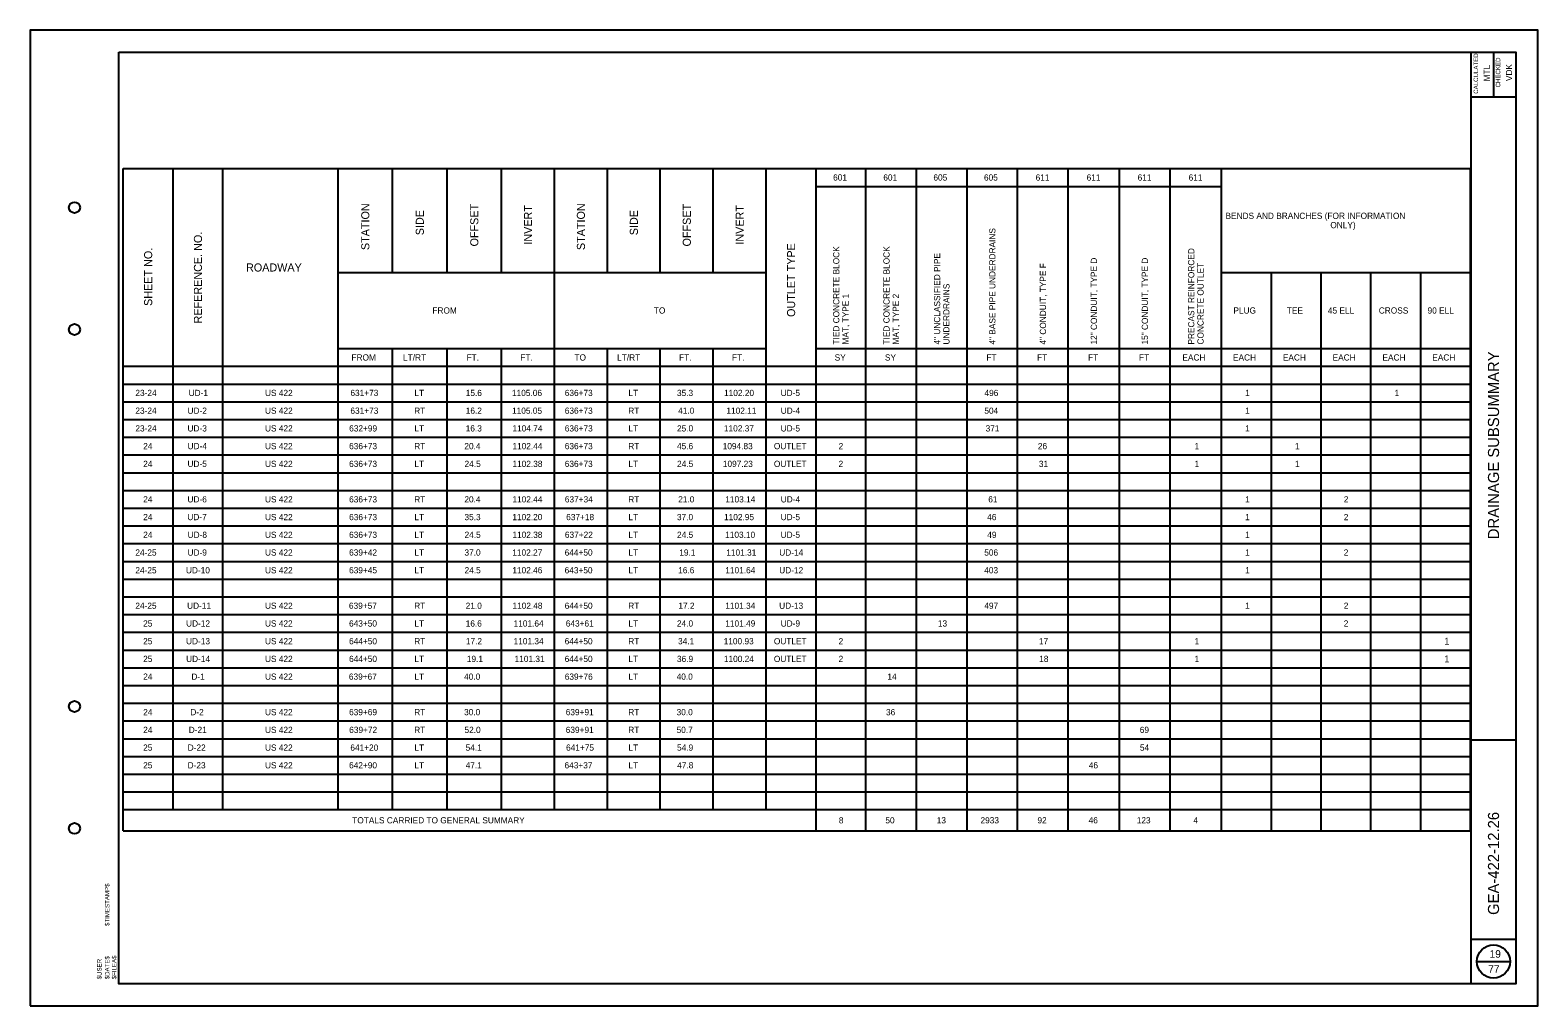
# Model space of a CAD drawing. Extents: x 0 to 34, y 0 to 22.
import ezdxf

# ---------------------------------------------------------------- set-up
doc = ezdxf.new("R2010")
doc.units = 0
for name, color, linetype in [('SH_Border', 7, 'Continuous'), ('SH_Cut_Line', 7, 'Continuous'), ('SH_Data', 7, 'Continuous'), ('SH_Text', 7, 'Continuous')]:
    doc.layers.add(name, color=color, linetype=linetype)

msp = doc.modelspace()

# ---------------------------------------------------------------- linework, layer by layer
at = {"layer": 'SH_Border'}
for p, q in [((32.5, 0.5), (32.5, 21.5)), ((33, 21.5), (33, 20.5)), ((32.5, 20.5), (33.5, 20.5)), ((32.5, 6), (33.5, 6)), ((32.5, 1.5), (33.5, 1.5))]:
    msp.add_line(p, q, dxfattribs=at)
msp.add_lwpolyline([(2, 21.5), (33.5, 21.5), (33.5, 0.5), (2, 0.5)], close=True, dxfattribs=at)
for centre in [(1, 18), (1, 15.25), (1, 6.75), (1, 4)]:
    msp.add_circle(centre, 0.125, dxfattribs=at)
at = {"layer": 'SH_Cut_Line'}
msp.add_lwpolyline([(0, 0), (34, 0), (34, 22), (0, 22)], close=True, dxfattribs=at)
at = {"layer": 'SH_Data'}
msp.add_line((32.625, 1), (33.375, 1), dxfattribs=at)
msp.add_circle((33, 1), 0.375, dxfattribs=at)
at = {"layer": 'SH_Text'}
for p, q in [((2.099, 18.878), (2.099, 18.878)), ((2.099, 18.878), (32.484, 18.878)), ((2.099, 3.944), (2.099, 18.878)), ((3.222, 4.424), (3.222, 18.878)), ((4.346, 4.424), (4.346, 18.878)), ((6.944, 4.424), (6.944, 18.878)), ((8.172, 16.539), (8.172, 18.878)), ((9.401, 16.539), (9.401, 18.878)), ((10.63, 16.539), (10.63, 18.878)), ((11.824, 4.424), (11.824, 18.878)), ((13.017, 16.539), (13.017, 18.878)), ((14.211, 16.539), (14.211, 18.878)), ((15.405, 16.539), (15.405, 18.878)), ((16.598, 4.424), (16.598, 18.878)), ((17.722, 3.944), (17.722, 18.878)), ((18.845, 3.944), (18.845, 18.878)), ((19.986, 3.944), (19.986, 18.878)), ((21.127, 3.944), (21.127, 18.878)), ((22.268, 3.944), (22.268, 18.878)), ((23.409, 3.944), (23.409, 18.878)), ((24.568, 3.944), (24.568, 18.878)), ((25.709, 3.944), (25.709, 18.878)), ((26.867, 3.944), (26.867, 18.878)), ((32.484, 3.944), (32.484, 18.878)), ((17.722, 18.478), (26.867, 18.478)), ((6.944, 16.539), (16.598, 16.539)), ((26.867, 16.539), (32.484, 16.539)), ((27.991, 3.944), (27.991, 16.539)), ((29.114, 3.944), (29.114, 16.539)), ((30.237, 3.944), (30.237, 16.539)), ((31.361, 3.944), (31.361, 16.539)), ((6.944, 14.82), (16.598, 14.82)), ((8.172, 4.424), (8.172, 14.82)), ((9.401, 4.424), (9.401, 14.82)), ((10.63, 4.424), (10.63, 14.82)), ((13.017, 4.424), (13.017, 14.82)), ((14.211, 4.424), (14.211, 14.82)), ((15.405, 4.424), (15.405, 14.82)), ((17.722, 14.82), (32.484, 14.82)), ((2.099, 14.42), (32.484, 14.42)), ((16.598, 14.42), (32.484, 14.42)), ((2.099, 14.02), (32.484, 14.02)), ((2.099, 13.62), (32.484, 13.62)), ((2.099, 13.22), (32.484, 13.22)), ((2.099, 12.821), (32.484, 12.821)), ((2.099, 12.421), (32.484, 12.421)), ((2.099, 12.021), (32.484, 12.021)), ((2.099, 11.621), (32.484, 11.621)), ((2.099, 11.221), (32.484, 11.221)), ((2.099, 10.821), (32.484, 10.821)), ((2.099, 10.422), (32.484, 10.422)), ((2.099, 10.022), (32.484, 10.022)), ((2.099, 9.622), (32.484, 9.622)), ((2.099, 9.222), (32.484, 9.222)), ((2.099, 8.822), (32.484, 8.822)), ((2.099, 8.422), (32.484, 8.422)), ((2.099, 8.023), (32.484, 8.023)), ((2.099, 7.623), (32.484, 7.623)), ((2.099, 7.223), (32.484, 7.223)), ((2.099, 6.823), (32.484, 6.823)), ((2.099, 6.423), (32.484, 6.423)), ((2.099, 6.023), (32.484, 6.023)), ((2.099, 5.624), (32.484, 5.624)), ((2.099, 5.224), (32.484, 5.224)), ((2.099, 4.824), (32.484, 4.824)), ((2.099, 4.424), (32.484, 4.424)), ((2.099, 3.944), (32.484, 3.944))]:
    msp.add_line(p, q, dxfattribs=at)

# ---------------------------------------------------------------- texts
at = {"layer": 'SH_Data'}
for s, height, rotation, p in [('CALCULATED', 0.1, 90, (32.652, 20.565)), ('MTL', 0.14, 90, (32.92, 20.844)), ('CHECKED', 0.1, 90, (33.152, 20.708)), ('VDK', 0.14, 90, (33.42, 20.851)), ('DRAINAGE SUBSUMMARY', 0.25, 90, (33.125, 10.521)), (' GEA-422-12.26 ', 0.25, 90, (33.125, 1.957)), ('$TIMESTAMP$', 0.1, 89.9931, (1.788, 1.8)), ('$USER', 0.1, 89.9931, (1.611, 0.598)), ('$DATE$', 0.1, 89.9931, (1.788, 0.598)), ('$FILEA$', 0.1, 89.9931, (1.944, 0.598))]:
    msp.add_text(s, height=height, rotation=rotation, dxfattribs=at).set_placement(p)
for s, p in [('19', (32.913, 1.085)), ('77', (32.882, 0.745))]:
    msp.add_text(s, height=0.17, dxfattribs=at).set_placement(p)
at = {"layer": 'SH_Text'}
for s, height, p in [('601', 0.14, (18.108, 18.608)), ('601', 0.14, (19.24, 18.608)), ('605', 0.14, (20.369, 18.608)), ('605', 0.14, (21.51, 18.608)), ('611', 0.14, (22.675, 18.608)), ('611', 0.14, (23.825, 18.608)), ('611', 0.14, (24.975, 18.608)), ('611', 0.14, (26.125, 18.608)), ('BENDS AND BRANCHES (FOR INFORMATION', 0.14, (26.956, 17.744)), ('ONLY)', 0.14, (29.32, 17.534)), ('ROADWAY', 0.182, (4.868, 16.558)), ('FROM', 0.14, (9.071, 15.609)), ('TO', 0.14, (14.065, 15.609)), ('PLUG', 0.14, (27.135, 15.609)), ('TEE', 0.14, (28.339, 15.609)), ('45 ELL', 0.14, (29.266, 15.609)), ('CROSS', 0.14, (30.413, 15.609)), ('90 ELL', 0.14, (31.513, 15.609)), ('FROM', 0.14, (7.246, 14.55)), ('LT/RT', 0.14, (8.409, 14.55)), ('FT.', 0.14, (9.841, 14.55)), ('FT.', 0.14, (11.053, 14.55)), ('TO', 0.14, (12.275, 14.55)), ('LT/RT', 0.14, (13.237, 14.55)), ('FT.', 0.14, (14.634, 14.55)), ('FT.', 0.14, (15.827, 14.55)), ('SY', 0.14, (18.143, 14.55)), ('SY', 0.14, (19.276, 14.55)), ('FT', 0.14, (21.566, 14.55)), ('FT', 0.14, (22.707, 14.55)), ('FT', 0.14, (23.857, 14.55)), ('FT', 0.14, (25.006, 14.55)), ('EACH', 0.14, (25.984, 14.55)), ('EACH', 0.14, (27.125, 14.55)), ('EACH', 0.14, (28.249, 14.55)), ('EACH', 0.14, (29.372, 14.55)), ('EACH', 0.14, (30.496, 14.55)), ('EACH', 0.14, (31.619, 14.55)), ('23-24', 0.14, (2.373, 13.75)), ('UD-1', 0.14, (3.573, 13.75)), ('US 422', 0.14, (5.296, 13.75)), ('631+73', 0.14, (7.222, 13.75)), ('LT', 0.14, (8.665, 13.75)), ('15.6', 0.14, (9.823, 13.75)), ('1105.06', 0.14, (10.866, 13.75)), ('636+73', 0.14, (12.056, 13.75)), ('LT', 0.14, (13.492, 13.75)), ('35.3', 0.14, (14.586, 13.75)), ('1102.20', 0.14, (15.648, 13.75)), ('UD-5', 0.14, (16.924, 13.75)), ('496', 0.14, (21.521, 13.75)), ('1', 0.14, (27.4, 13.75)), ('1', 0.14, (30.77, 13.75)), ('23-24', 0.14, (2.373, 13.35)), ('UD-2', 0.14, (3.549, 13.35)), ('US 422', 0.14, (5.296, 13.35)), ('631+73', 0.14, (7.222, 13.35)), ('RT', 0.14, (8.661, 13.35)), ('16.2', 0.14, (9.823, 13.35)), ('1105.05', 0.14, (10.867, 13.35)), ('636+73', 0.14, (12.056, 13.35)), ('RT', 0.14, (13.488, 13.35)), ('41.0', 0.14, (14.613, 13.35)), ('1102.11', 0.14, (15.701, 13.35)), ('UD-4', 0.14, (16.926, 13.35)), ('504', 0.14, (21.518, 13.35)), ('1', 0.14, (27.4, 13.35)), ('23-24', 0.14, (2.373, 12.951)), ('UD-3', 0.14, (3.548, 12.951)), ('US 422', 0.14, (5.296, 12.951)), ('632+99', 0.14, (7.194, 12.951)), ('LT', 0.14, (8.665, 12.951)), ('16.3', 0.14, (9.822, 12.951)), ('1104.74', 0.14, (10.876, 12.951)), ('636+73', 0.14, (12.056, 12.951)), ('LT', 0.14, (13.492, 12.951)), ('25.0', 0.14, (14.587, 12.951)), ('1102.37', 0.14, (15.645, 12.951)), ('UD-5', 0.14, (16.924, 12.951)), ('371', 0.14, (21.547, 12.951)), ('1', 0.14, (27.4, 12.951)), ('24', 0.14, (2.549, 12.551)), ('UD-4', 0.14, (3.55, 12.551)), ('US 422', 0.14, (5.296, 12.551)), ('636+73', 0.14, (7.193, 12.551)), ('RT', 0.14, (8.661, 12.551)), ('20.4', 0.14, (9.792, 12.551)), ('1102.44', 0.14, (10.876, 12.551)), ('636+73', 0.14, (12.056, 12.551)), ('RT', 0.14, (13.488, 12.551)), ('45.6', 0.14, (14.587, 12.551)), ('1094.83', 0.14, (15.618, 12.551)), ('OUTLET', 0.14, (16.772, 12.551)), ('2', 0.14, (18.231, 12.551)), ('26', 0.14, (22.725, 12.551)), ('1', 0.14, (26.259, 12.551)), ('1', 0.14, (28.523, 12.551)), ('24', 0.14, (2.549, 12.151)), ('UD-5', 0.14, (3.548, 12.151)), ('US 422', 0.14, (5.296, 12.151)), ('636+73', 0.14, (7.193, 12.151)), ('LT', 0.14, (8.665, 12.151)), ('24.5', 0.14, (9.796, 12.151)), ('1102.38', 0.14, (10.876, 12.151)), ('636+73', 0.14, (12.056, 12.151)), ('LT', 0.14, (13.492, 12.151)), ('24.5', 0.14, (14.588, 12.151)), ('1097.23', 0.14, (15.621, 12.151)), ('OUTLET', 0.14, (16.772, 12.151)), ('2', 0.14, (18.231, 12.151)), ('31', 0.14, (22.748, 12.151)), ('1', 0.14, (26.259, 12.151)), ('1', 0.14, (28.523, 12.151)), ('24', 0.14, (2.549, 11.351)), ('UD-6', 0.14, (3.548, 11.351)), ('US 422', 0.14, (5.296, 11.351)), ('636+73', 0.14, (7.193, 11.351)), ('RT', 0.14, (8.661, 11.351)), ('20.4', 0.14, (9.792, 11.351)), ('1102.44', 0.14, (10.876, 11.351)), ('637+34', 0.14, (12.058, 11.351)), ('RT', 0.14, (13.488, 11.351)), ('21.0', 0.14, (14.614, 11.351)), ('1103.14', 0.14, (15.676, 11.351)), ('UD-4', 0.14, (16.926, 11.351)), ('61', 0.14, (21.607, 11.351)), ('1', 0.14, (27.4, 11.351)), ('2', 0.14, (29.623, 11.351)), ('24', 0.14, (2.549, 10.951)), ('UD-7', 0.14, (3.545, 10.951)), ('US 422', 0.14, (5.296, 10.951)), ('636+73', 0.14, (7.193, 10.951)), ('LT', 0.14, (8.665, 10.951)), ('35.3', 0.14, (9.794, 10.951)), ('1102.20', 0.14, (10.874, 10.951)), ('637+18', 0.14, (12.088, 10.951)), ('LT', 0.14, (13.492, 10.951)), ('37.0', 0.14, (14.586, 10.951)), ('1102.95', 0.14, (15.648, 10.951)), ('UD-5', 0.14, (16.924, 10.951)), ('46', 0.14, (21.582, 10.951)), ('1', 0.14, (27.4, 10.951)), ('2', 0.14, (29.623, 10.951)), ('24', 0.14, (2.549, 10.552)), ('UD-8', 0.14, (3.551, 10.552)), ('US 422', 0.14, (5.296, 10.552)), ('636+73', 0.14, (7.193, 10.552)), ('LT', 0.14, (8.665, 10.552)), ('24.5', 0.14, (9.796, 10.552)), ('1102.38', 0.14, (10.876, 10.552)), ('637+22', 0.14, (12.059, 10.552)), ('LT', 0.14, (13.492, 10.552)), ('24.5', 0.14, (14.588, 10.552)), ('1103.10', 0.14, (15.673, 10.552)), ('UD-5', 0.14, (16.924, 10.552)), ('49', 0.14, (21.584, 10.552)), ('1', 0.14, (27.4, 10.552)), ('24-25', 0.14, (2.372, 10.152)), ('UD-9', 0.14, (3.549, 10.152)), ('US 422', 0.14, (5.296, 10.152)), ('639+42', 0.14, (7.193, 10.152)), ('LT', 0.14, (8.665, 10.152)), ('37.0', 0.14, (9.794, 10.152)), ('1102.27', 0.14, (10.873, 10.152)), ('644+50', 0.14, (12.054, 10.152)), ('LT', 0.14, (13.492, 10.152)), ('19.1', 0.14, (14.639, 10.152)), ('1101.31', 0.14, (15.699, 10.152)), ('UD-14', 0.14, (16.893, 10.152)), ('506', 0.14, (21.516, 10.152)), ('1', 0.14, (27.4, 10.152)), ('2', 0.14, (29.623, 10.152)), ('24-25', 0.14, (2.372, 9.752)), ('UD-10', 0.14, (3.513, 9.752)), ('US 422', 0.14, (5.296, 9.752)), ('639+45', 0.14, (7.192, 9.752)), ('LT', 0.14, (8.665, 9.752)), ('24.5', 0.14, (9.796, 9.752)), ('1102.46', 0.14, (10.874, 9.752)), ('643+50', 0.14, (12.053, 9.752)), ('LT', 0.14, (13.492, 9.752)), ('16.6', 0.14, (14.614, 9.752)), ('1101.64', 0.14, (15.676, 9.752)), ('UD-12', 0.14, (16.892, 9.752)), ('403', 0.14, (21.515, 9.752)), ('1', 0.14, (27.4, 9.752)), ('24-25', 0.14, (2.372, 8.952)), ('UD-11', 0.14, (3.539, 8.952)), ('US 422', 0.14, (5.296, 8.952)), ('639+57', 0.14, (7.189, 8.952)), ('RT', 0.14, (8.661, 8.952)), ('21.0', 0.14, (9.822, 8.952)), ('1102.48', 0.14, (10.877, 8.952)), ('644+50', 0.14, (12.054, 8.952)), ('RT', 0.14, (13.488, 8.952)), ('17.2', 0.14, (14.618, 8.952)), ('1101.34', 0.14, (15.676, 8.952)), ('UD-13', 0.14, (16.891, 8.952)), ('497', 0.14, (21.518, 8.952)), ('1', 0.14, (27.4, 8.952)), ('2', 0.14, (29.623, 8.952)), ('25', 0.14, (2.548, 8.552)), ('UD-12', 0.14, (3.516, 8.552)), ('US 422', 0.14, (5.296, 8.552)), ('643+50', 0.14, (7.191, 8.552)), ('LT', 0.14, (8.665, 8.552)), ('16.6', 0.14, (9.822, 8.552)), ('1101.64', 0.14, (10.902, 8.552)), ('643+61', 0.14, (12.079, 8.552)), ('LT', 0.14, (13.492, 8.552)), ('24.0', 0.14, (14.586, 8.552)), ('1101.49', 0.14, (15.676, 8.552)), ('UD-9', 0.14, (16.925, 8.552)), ('13', 0.14, (20.47, 8.552)), ('2', 0.14, (29.623, 8.552)), ('25', 0.14, (2.548, 8.152)), ('UD-13', 0.14, (3.515, 8.152)), ('US 422', 0.14, (5.296, 8.152)), ('644+50', 0.14, (7.192, 8.152)), ('RT', 0.14, (8.661, 8.152)), ('17.2', 0.14, (9.826, 8.152)), ('1101.34', 0.14, (10.902, 8.152)), ('644+50', 0.14, (12.054, 8.152)), ('RT', 0.14, (13.488, 8.152)), ('34.1', 0.14, (14.611, 8.152)), ('1100.93', 0.14, (15.64, 8.152)), ('OUTLET', 0.14, (16.772, 8.152)), ('2', 0.14, (18.231, 8.152)), ('17', 0.14, (22.749, 8.152)), ('1', 0.14, (26.259, 8.152)), ('1', 0.154, (31.891, 8.145)), ('25', 0.14, (2.548, 7.753)), ('UD-14', 0.14, (3.517, 7.753)), ('US 422', 0.14, (5.296, 7.753)), ('644+50', 0.14, (7.192, 7.753)), ('LT', 0.14, (8.665, 7.753)), ('19.1', 0.14, (9.847, 7.753)), ('1101.31', 0.14, (10.924, 7.753)), ('644+50', 0.14, (12.054, 7.753)), ('LT', 0.14, (13.492, 7.753)), ('36.9', 0.14, (14.586, 7.753)), ('1100.24', 0.14, (15.644, 7.753)), ('OUTLET', 0.14, (16.772, 7.753)), ('2', 0.14, (18.231, 7.753)), ('18', 0.14, (22.755, 7.753)), ('1', 0.14, (26.259, 7.753)), ('1', 0.154, (31.891, 7.746)), ('24', 0.14, (2.549, 7.353)), ('D-1', 0.14, (3.636, 7.353)), ('US 422', 0.14, (5.296, 7.353)), ('639+67', 0.14, (7.188, 7.353)), ('LT', 0.14, (8.665, 7.353)), ('40.0', 0.14, (9.786, 7.353)), ('639+76', 0.14, (12.056, 7.353)), ('LT', 0.14, (13.492, 7.353)), ('40.0', 0.14, (14.579, 7.353)), ('14', 0.14, (19.331, 7.353)), ('24', 0.14, (2.549, 6.553)), ('D-2', 0.14, (3.613, 6.553)), ('US 422', 0.14, (5.296, 6.553)), ('639+69', 0.14, (7.192, 6.553)), ('RT', 0.14, (8.661, 6.553)), ('30.0', 0.14, (9.786, 6.553)), ('639+91', 0.14, (12.078, 6.553)), ('RT', 0.14, (13.488, 6.553)), ('30.0', 0.14, (14.578, 6.553)), ('36', 0.14, (19.3, 6.553)), ('24', 0.14, (2.549, 6.153)), ('D-21', 0.14, (3.576, 6.153)), ('US 422', 0.14, (5.296, 6.153)), ('639+72', 0.14, (7.195, 6.153)), ('RT', 0.14, (8.661, 6.153)), ('52.0', 0.14, (9.795, 6.153)), ('639+91', 0.14, (12.078, 6.153)), ('RT', 0.14, (13.488, 6.153)), ('50.7', 0.14, (14.578, 6.153)), ('69', 0.14, (25.023, 6.153)), ('25', 0.14, (2.548, 5.753)), ('D-22', 0.14, (3.553, 5.753)), ('US 422', 0.14, (5.296, 5.753)), ('641+20', 0.14, (7.221, 5.753)), ('LT', 0.14, (8.665, 5.753)), ('54.1', 0.14, (9.82, 5.753)), ('641+75', 0.14, (12.085, 5.753)), ('LT', 0.14, (13.492, 5.753)), ('54.9', 0.14, (14.588, 5.753)), ('54', 0.14, (25.026, 5.753)), ('25', 0.14, (2.548, 5.354)), ('D-23', 0.14, (3.551, 5.354)), ('US 422', 0.14, (5.296, 5.354)), ('642+90', 0.14, (7.192, 5.354)), ('LT', 0.14, (8.665, 5.354)), ('47.1', 0.14, (9.821, 5.354)), ('643+37', 0.14, (12.051, 5.354)), ('LT', 0.14, (13.492, 5.354)), ('47.8', 0.14, (14.591, 5.354)), ('46', 0.14, (23.873, 5.354)), ('TOTALS CARRIED TO GENERAL SUMMARY', 0.14, (7.263, 4.114)), ('8', 0.14, (18.237, 4.114)), ('50', 0.14, (19.286, 4.114)), ('13', 0.14, (20.444, 4.114)), ('2933', 0.14, (21.431, 4.114)), ('92', 0.14, (22.715, 4.114)), ('46', 0.14, (23.87, 4.114)), ('123', 0.14, (24.955, 4.114)), ('4', 0.14, (26.231, 4.114))]:
    msp.add_text(s, height=height, dxfattribs=at).set_placement(p)
for s, height, p in [('STATION', 0.182, (7.649, 17.041)), ('OFFSET', 0.182, (10.107, 17.123)), ('INVERT', 0.182, (11.318, 17.163)), ('STATION', 0.182, (12.511, 17.041)), ('OFFSET', 0.182, (14.899, 17.123)), ('INVERT', 0.182, (16.092, 17.163)), ('SIDE', 0.182, (8.878, 17.376)), ('SIDE', 0.182, (13.705, 17.376)), ('REFERENCE. NO.', 0.182, (3.875, 15.387)), ('4" BASE PIPE UNDERDRAINS', 0.14, (21.768, 14.911)), ('SHEET NO.', 0.182, (2.752, 15.782)), ('OUTLET TYPE', 0.182, (17.251, 15.533)), ('TIED CONCRETE BLOCK', 0.14, (18.248, 14.911)), ('TIED CONCRETE BLOCK', 0.14, (19.381, 14.911)), ('PRECAST REINFORCED', 0.14, (26.253, 14.911)), ('4" UNCLASSIFIED PIPE', 0.14, (20.522, 14.911)), ('4" CONDUIT, TYPE F', 0.14, (22.909, 14.911)), ('12" CONDUIT, TYPE D', 0.14, (24.058, 14.911)), ('15" CONDUIT, TYPE D', 0.14, (25.208, 14.911)), ('CONCRETE OUTLET', 0.14, (26.463, 14.911)), ('MAT, TYPE 1', 0.14, (18.458, 14.911)), ('MAT, TYPE 2', 0.14, (19.591, 14.911)), ('UNDERDRAINS', 0.14, (20.732, 14.911))]:
    msp.add_text(s, height=height, rotation=90, dxfattribs=at).set_placement(p)

doc.saveas('drawing.dxf')
